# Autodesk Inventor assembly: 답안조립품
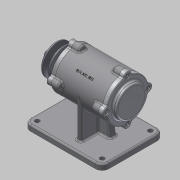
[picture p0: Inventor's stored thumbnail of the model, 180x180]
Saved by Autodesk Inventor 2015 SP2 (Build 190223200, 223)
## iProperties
Created: 2015-12
Part Number: 답안조립품
Document SubType Name: Assembly
Designer: AMC
Author: AMC
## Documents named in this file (11)
- C:\Users\AMC\Desktop\451207V1004\답안조립품.iam
- C:\Users\AMC\Desktop\451207V1004\본체.ipt
- C:\Users\AMC\Desktop\451207V1004\커버.ipt
- C:\Users\AMC\Desktop\451207V1004\커버2.ipt
- C:\Users\AMC\Desktop\451207V1004\베어링 6204.ipt
- C:\Users\AMC\Desktop\451207V1004\오일실.ipt
- C:\Users\AMC\Desktop\451207V1004\축.ipt
- C:\Users\AMC\Desktop\451207V1004\V-벨트풀리.ipt
- C:\Users\AMC\Desktop\451207V1004\키(4 x 4 x 12).ipt
- C:\Users\AMC\Desktop\451207V1004\너트 M12x1.25.ipt
- C:\Users\AMC\Desktop\451207V1004\볼트 M4 x 12.ipt
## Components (6 placed, 5 different names)
1. KS B 2023 6204 - 20 x 47 x 14:1
2. KS B 2023 6204 - 20 x 47 x 14:2
3. KS B 2804 D D - 20 32 8:1
4. V-벨트풀리:1
5. KS B 1311 (I) 4 x 4 x 12:1 — 강체:1
6. KS B 1012 클래스 1 일반 - 미터 M12x1.25:1
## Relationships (1: WeldJoint 1)
- 강체:1 [WeldJoint]: KS B 1311 (I) 4 x 4 x 12:1
